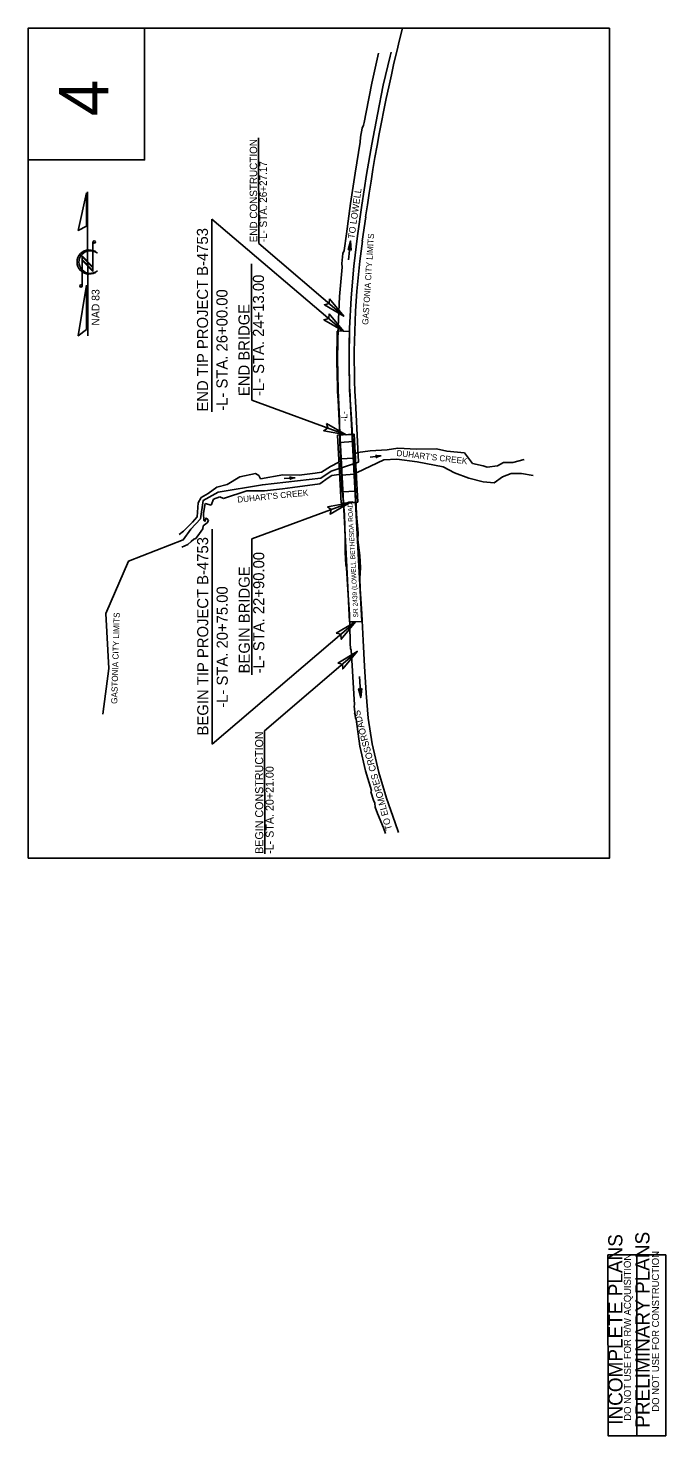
# Model space of a CAD drawing. Extents: x 1372027 to 1374286, y 553832 to 556743.
# Drawn here: x 1373433 to 1373952, y 555599 to 556743 of the extents above; entities that cross this region are included whole.
import ezdxf

# ---------------------------------------------------------------- set-up
doc = ezdxf.new("R2010")
doc.units = 0
for name, color, linetype in [('Default', 7, 'Continuous'), ('Prop Dimension', 7, 'Continuous'), ('Prop Dimension Text', 7, 'Continuous'), ('Prop EOT', 7, 'Continuous'), ('Prop Horizontal Alignment', 7, 'Continuous'), ('Prop Horizontal Alignment Curve and Spiral Data', 7, 'Continuous'), ('Prop Horizontal Alignment Station Label', 7, 'Continuous'), ('Prop Horizontal Alignment Tick Small', 7, 'Continuous'), ('Prop North Arrow for Plan Sheets CELL', 7, 'Continuous'), ('Prop Roadway Bridge', 7, 'Continuous'), ('Prop Shade Light', 7, 'Continuous'), ('Prop Terminator CELL', 7, 'Continuous'), ('Sheet Layout Plan Border', 7, 'Continuous'), ('Sheet North Arrow CELL', 7, 'Continuous'), ('Sheet Plan Layout CELL', 7, 'Continuous'), ('Sheet Plot Border Inside CELL', 7, 'Continuous')]:
    doc.layers.add(name, color=color, linetype=linetype)

msp = doc.modelspace()

# ---------------------------------------------------------------- linework, layer by layer
at = {"layer": 'Default'}
for p, q in [((1373693.8, 556554.9), (1373695.4, 556570.2)), ((1373702.6, 556216.3), (1373703.7, 556199.2))]:
    msp.add_line(p, q, dxfattribs=at)
at = {"layer": 'Prop Dimension'}
for p, q in [((1373620.7, 556568.1), (1373620.6, 556654)), ((1373689.6, 556496.9), (1373582.6, 556588)), ((1373582.7, 556431.4), (1373582.6, 556588)), ((1373689.9, 556509.1), (1373620.7, 556568.1)), ((1373615, 556440.9), (1373614.9, 556551.7)), ((1373615, 556440.9), (1373691.7, 556412.8)), ((1373694.5, 556357.6), (1373615.1, 556328.3)), ((1373582.9, 556161.3), (1373582.8, 556336)), ((1373615.2, 556217.7), (1373615.1, 556328.3)), ((1373582.9, 556161.3), (1373699.5, 556260.9)), ((1373625.5, 556172.3), (1373700.8, 556236.7)), ((1373625.6, 556072.3), (1373625.5, 556172.3))]:
    msp.add_line(p, q, dxfattribs=at)
at = {"layer": 'Prop Dimension Text'}
for p, q in [((1373684.9, 556412.5), (1373698.4, 556413.2)), ((1373687.8, 556357.2), (1373684.9, 556412.5)), ((1373698.4, 556413.2), (1373701.3, 556357.9)), ((1373701.3, 556357.9), (1373687.8, 556357.2))]:
    msp.add_line(p, q, dxfattribs=at)
for points in [[(1373433.3, 556068.7), (1373433.3, 556743.1), (1373905.8, 556743.1), (1373905.8, 556068.7)], [(1373433.3, 556636.1), (1373433.3, 556743.1), (1373528, 556743.1), (1373528, 556636.1)]]:
    msp.add_lwpolyline(points, close=True, dxfattribs=at)
at = {"layer": 'Prop EOT'}
for p, q in [((1373684.6, 556497.1), (1373694.5, 556496.8)), ((1373692.3, 556305.6), (1373685.3, 556440.9)), ((1373704.5, 556261.2), (1373695.2, 556441.4)), ((1373692.3, 556305.6), (1373694.6, 556260.7)), ((1373694.6, 556260.7), (1373699.5, 556260.9)), ((1373699.5, 556260.9), (1373704.5, 556261.2))]:
    msp.add_line(p, q, dxfattribs=at)
for radius in [695.7, 685.8]:
    msp.add_arc((1374380, 556476.8), radius, 178.3325, 182.9585, dxfattribs=at)
at = {"layer": 'Prop Horizontal Alignment'}
msp.add_lwpolyline([(1373951.7, 555599.5), (1373928.2, 555599.5), (1373928.1, 555746.5), (1373951.6, 555746.5)], close=True, dxfattribs=at)
at = {"layer": 'Prop Horizontal Alignment Curve and Spiral Data'}
for p, q in [((1373687.3, 556393.2), (1373698, 556393.9)), ((1373698.6, 556380.7), (1373687.9, 556380))]:
    msp.add_line(p, q, dxfattribs=at)
msp.add_lwpolyline([(1373699.5, 556367), (1373688.5, 556366.3), (1373686.6, 556406.6), (1373697.5, 556407.3), (1373699.5, 556367)], dxfattribs=at)
at = {"layer": 'Prop Horizontal Alignment Tick Small'}
msp.add_lwpolyline([(1373928.2, 555599.5), (1373904.7, 555599.5), (1373904.6, 555746.5), (1373928.1, 555746.5)], close=True, dxfattribs=at)
at = {"layer": 'Prop North Arrow for Plan Sheets CELL'}
for points in [[(1373693.4, 556563.1), (1373695.4, 556570.2), (1373696, 556562.8), (1373694.8, 556563.9)], [(1373704.5, 556206.5), (1373703.7, 556199.2), (1373701.9, 556206.4), (1373703.3, 556205.6)]]:
    msp.add_lwpolyline(points, close=True, dxfattribs=at)
at = {"layer": 'Prop Roadway Bridge'}
for p, q in [((1373684.9, 556412.5), (1373698.4, 556413.2)), ((1373687.8, 556357.2), (1373684.9, 556412.5)), ((1373701.3, 556357.9), (1373698.4, 556413.2)), ((1373687.8, 556357.2), (1373701.3, 556357.9))]:
    msp.add_line(p, q, dxfattribs=at)
at = {"layer": 'Prop Shade Light'}
msp.add_line((1373685.3, 556440.9), (1373686.7, 556412.6), dxfattribs=at)
for points in [[(1373694.5, 556496.8), (1373689.6, 556496.9), (1373684.6, 556497.1)], [(1373686.7, 556412.6), (1373696.6, 556413.1), (1373695.2, 556441.4)]]:
    msp.add_lwpolyline(points, dxfattribs=at)
msp.add_lwpolyline([(1373699.5, 556357.8), (1373689.6, 556357.3), (1373692.3, 556305.6), (1373694.6, 556260.7), (1373699.5, 556260.9), (1373704.5, 556261.2), (1373702.1, 556306.1)], close=True, dxfattribs=at)
for radius in [695.7, 685.8]:
    msp.add_arc((1374380, 556476.8), radius, 178.3325, 182.9585, dxfattribs=at)
at = {"layer": 'Prop Terminator CELL'}
for points in [[(1373704.9, 556570), (1373707.7, 556589.8)], [(1373701.9, 556390.6), (1373699.3, 556440)], [(1373493.9, 556185.7), (1373498.9, 556222.8), (1373496.4, 556267.5), (1373514.9, 556310.1), (1373559.4, 556327.4), (1373565.5, 556336), (1373573.4, 556344.6), (1373575.6, 556359.4), (1373587.9, 556366.2), (1373623.8, 556372.2), (1373671.1, 556377.6), (1373679.6, 556383.3), (1373693, 556387.5), (1373701.9, 556390.6)]]:
    msp.add_lwpolyline(points, dxfattribs=at)
for points in [[(1373678.2, 556523.2), (1373689.9, 556509.1), (1373674.1, 556518.4), (1373677.9, 556519.4)], [(1373677.9, 556511), (1373689.6, 556496.9), (1373673.7, 556506.2), (1373677.6, 556507.2)], [(1373675.8, 556421.9), (1373691.7, 556412.8), (1373673.6, 556416), (1373676.8, 556418.3)], [(1373676.6, 556354.3), (1373694.5, 556357.6), (1373678.7, 556348.3), (1373679.7, 556352.1)], [(1373683.8, 556251.6), (1373699.5, 556260.9), (1373687.8, 556246.7), (1373687.5, 556250.7)], [(1373685.1, 556227.3), (1373700.8, 556236.7), (1373689.1, 556222.5), (1373688.8, 556226.4)]]:
    msp.add_lwpolyline(points, close=True, dxfattribs=at)
for centre, radius, start, end in [((1375157.8, 556386.7), 1464.3, 165.9137, 172.027), ((1374376.9, 556475.9), 678.5, 172.027, 183.0355)]:
    msp.add_arc(centre, radius, start, end, dxfattribs=at)
at = {"layer": 'Sheet Layout Plan Border'}
for p, q in [((1373698.9, 556397.3), (1373701.2, 556398.5)), ((1373699.4, 556394.6), (1373698.9, 556397.3)), ((1373701.2, 556398.5), (1373711.4, 556399.8)), ((1373720.2, 556395.7), (1373711.3, 556394.5)), ((1373711.4, 556399.8), (1373725.1, 556400.5)), ((1373715.6, 556396.1), (1373716.5, 556395.9)), ((1373715.8, 556395.1), (1373715.8, 556395.1)), ((1373716.5, 556395.9), (1373717.4, 556395.7)), ((1373717.4, 556395.7), (1373718.4, 556395.6)), ((1373717.5, 556394.9), (1373718.4, 556395.3)), ((1373718.4, 556395.6), (1373719.3, 556395.6)), ((1373718.4, 556395.3), (1373719.3, 556395.5)), ((1373719.3, 556395.5), (1373720.2, 556395.7)), ((1373719.3, 556395.6), (1373720.2, 556395.7)), ((1373725.1, 556400.5), (1373733.9, 556401.9)), ((1373733.9, 556401.9), (1373749.1, 556401.2)), ((1373749.1, 556401.2), (1373765.2, 556401.3)), ((1373765.2, 556401.3), (1373773.7, 556399.4)), ((1373773.7, 556399.4), (1373788.1, 556398.2)), ((1373788.1, 556398.2), (1373794.6, 556389.4)), ((1373671.8, 556382.4), (1373679, 556387.1)), ((1373679, 556387.1), (1373685.9, 556390.4)), ((1373685.9, 556390.4), (1373687.3, 556391.9)), ((1373698.2, 556393.2), (1373699.4, 556393.2)), ((1373699.4, 556393.2), (1373699.4, 556394.6)), ((1373700.7, 556382), (1373722.4, 556392.3)), ((1373715.9, 556394.1), (1373716.7, 556394.5)), ((1373716.7, 556394.5), (1373717.5, 556394.9)), ((1373722.4, 556392.3), (1373733, 556393)), ((1373733, 556393), (1373749.6, 556390.7)), ((1373749.6, 556390.7), (1373770.6, 556386.8)), ((1373770.6, 556386.8), (1373779.8, 556381.9)), ((1373794.6, 556389.4), (1373803.1, 556387.6)), ((1373803.1, 556387.6), (1373806.4, 556386.4)), ((1373806.4, 556386.4), (1373814.9, 556387.5)), ((1373814.9, 556387.5), (1373819.6, 556390.2)), ((1373819.6, 556390.2), (1373827.4, 556390.3)), ((1373827.4, 556390.3), (1373836.4, 556392.8)), ((1373586.6, 556370.1), (1373595.1, 556372.5)), ((1373595.1, 556372.5), (1373605.4, 556378.7)), ((1373605.4, 556378.7), (1373618.2, 556381.2)), ((1373618.2, 556381.2), (1373620.7, 556379.6)), ((1373620.7, 556379.6), (1373622.3, 556377.1)), ((1373622.3, 556377.1), (1373640.3, 556380.2)), ((1373640.3, 556380.2), (1373653.5, 556380)), ((1373650.3, 556377.9), (1373641.4, 556377.2)), ((1373645.8, 556378.6), (1373646.7, 556378.3)), ((1373645.9, 556377.6), (1373645.9, 556377.6)), ((1373645.9, 556376.5), (1373646.8, 556377)), ((1373646.7, 556378.3), (1373647.6, 556378.1)), ((1373646.8, 556377), (1373647.6, 556377.3)), ((1373647.6, 556378.1), (1373648.5, 556377.9)), ((1373647.6, 556377.3), (1373648.5, 556377.6)), ((1373648.3, 556370), (1373670.4, 556372.8)), ((1373648.5, 556377.9), (1373649.4, 556377.9)), ((1373648.5, 556377.6), (1373649.4, 556377.8)), ((1373649.4, 556377.8), (1373650.3, 556377.9)), ((1373649.4, 556377.9), (1373650.3, 556377.9)), ((1373653.5, 556380), (1373666.6, 556381.5)), ((1373666.6, 556381.5), (1373671.8, 556382.4)), ((1373670.4, 556372.8), (1373677.2, 556377.9)), ((1373677.2, 556377.9), (1373680.2, 556379.6)), ((1373680.2, 556379.6), (1373685.9, 556380.4)), ((1373698.8, 556381.6), (1373700.7, 556382)), ((1373779.8, 556381.9), (1373791.6, 556377.4)), ((1373791.6, 556377.4), (1373803.2, 556374.5)), ((1373803.2, 556374.5), (1373812.2, 556373.7)), ((1373812.2, 556373.7), (1373819, 556378.7)), ((1373819, 556378.7), (1373825.9, 556381.3)), ((1373825.9, 556381.3), (1373834.4, 556381.3)), ((1373834.4, 556381.3), (1373843.9, 556379.7)), ((1373571.6, 556357.6), (1373574, 556361.8)), ((1373574, 556361.8), (1373579.6, 556365.1)), ((1373579.6, 556365.1), (1373586.6, 556370.1)), ((1373584.1, 556360.5), (1373589.2, 556362.3)), ((1373589.2, 556362.3), (1373592.1, 556361)), ((1373592.1, 556361), (1373611.1, 556367.2)), ((1373611.1, 556367.2), (1373625.4, 556367.3)), ((1373625.4, 556367.3), (1373640, 556368.9)), ((1373640, 556368.9), (1373648.3, 556370)), ((1373570.8, 556346.2), (1373571.6, 556357.6)), ((1373570.8, 556346.2), (1373571.6, 556357.6)), ((1373575.8, 556349.2), (1373577.2, 556357)), ((1373577.2, 556357), (1373582.2, 556355.5)), ((1373582.2, 556355.5), (1373584.1, 556360.5)), ((1373559.7, 556334.4), (1373566.8, 556341.9)), ((1373566.8, 556341.9), (1373570.8, 556346.2)), ((1373575.2, 556336.3), (1373575.7, 556338.9)), ((1373575.7, 556338.9), (1373578.7, 556341.1)), ((1373576.1, 556343.1), (1373575.8, 556349.2)), ((1373576.8, 556342.4), (1373576.1, 556343.1)), ((1373578.1, 556345.2), (1373576.8, 556342.4)), ((1373578.6, 556344.8), (1373578.1, 556345.2)), ((1373579.9, 556343.2), (1373578.6, 556344.8)), ((1373578.7, 556341.1), (1373579.9, 556343.2)), ((1373556.1, 556331.8), (1373559.7, 556334.4)), ((1373565.7, 556326), (1373567.9, 556327.9)), ((1373567.9, 556327.9), (1373569.5, 556328.6)), ((1373569.5, 556328.6), (1373572.6, 556332.6)), ((1373572.6, 556332.6), (1373575.2, 556336.3)), ((1373558.2, 556321.4), (1373563, 556323.6)), ((1373563, 556323.6), (1373565.7, 556326))]:
    msp.add_line(p, q, dxfattribs=at)
at = {"layer": 'Sheet North Arrow CELL'}
for p, q in [((1373481.7, 556493.2), (1373481.6, 556610.2)), ((1373486, 556569.5), (1373486, 556545.5)), ((1373486, 556549.2), (1373477.1, 556558.1)), ((1373477.1, 556558.1), (1373477.1, 556533.7)), ((1373486, 556548.3), (1373477.1, 556557.3)), ((1373477.1, 556557.3), (1373477.1, 556555.1)), ((1373489.3, 556560.5), (1373489.5, 556560.4)), ((1373486, 556546.1), (1373477.1, 556555.1)), ((1373477.1, 556555.1), (1373486, 556546.1)), ((1373486, 556545.5), (1373477.1, 556554.4)), ((1373486, 556546.1), (1373486, 556548.3))]:
    msp.add_line(p, q, dxfattribs=at)
for points in [[(1373480.8, 556609.2), (1373474.1, 556578.8), (1373480.8, 556582.2)], [(1373480.7, 556534.4), (1373474.1, 556493.2), (1373480.7, 556498.4)]]:
    msp.add_lwpolyline(points, close=True, dxfattribs=at)
for centre in [(1373487, 556569.4), (1373476.2, 556533.7)]:
    msp.add_circle(centre, 0.954, dxfattribs=at)
for centre, radius, start, end in [((1373482.9, 556553.1), 9.83, 47.891, 312.445), ((1373483.8, 556553.1), 9.21, 53.146, 308.6797)]:
    msp.add_arc(centre, radius, start, end, dxfattribs=at)
at = {"layer": 'Sheet Plot Border Inside CELL'}
for points in [[(1373686.7, 556406.7), (1373686.3, 556425.7), (1373685.3, 556448.7), (1373684.8, 556474.9), (1373685.3, 556500.3), (1373686.3, 556525), (1373688.6, 556549), (1373688.2, 556551.8), (1373689.2, 556560.1), (1373690.1, 556562.4), (1373692, 556576), (1373695.4, 556600.7), (1373699.2, 556625.3), (1373703.3, 556650.5), (1373703.4, 556654.5), (1373704.9, 556661.9), (1373705.8, 556664.3), (1373706.5, 556666.6), (1373708.1, 556674.8), (1373712.8, 556698.5), (1373718.1, 556722.7)], [(1373728.4, 556723.6), (1373727.5, 556720.4), (1373722, 556696.7), (1373717.3, 556673.1), (1373712.7, 556648.8), (1373708.4, 556624.1), (1373704.6, 556599.3), (1373701.1, 556574.4), (1373698, 556549.8), (1373695.9, 556524.1), (1373694.6, 556499), (1373694.3, 556474.4), (1373694.6, 556449.3), (1373696.1, 556425.4), (1373697.2, 556407.7)], [(1373702.8, 556159.9), (1373699.9, 556181.7), (1373699.3, 556182.4), (1373698.2, 556192.2), (1373698.6, 556193.4), (1373698.1, 556202.4), (1373696.6, 556225.4), (1373695.9, 556237.7), (1373695.4, 556239), (1373695.2, 556243.1), (1373695.2, 556245.6), (1373694.4, 556266.7), (1373693.2, 556286.9), (1373692, 556304.6), (1373691.6, 556307.1), (1373691.1, 556317.5), (1373690.9, 556327.6), (1373690.4, 556347.9), (1373688.9, 556366.1)], [(1373699.3, 556366.7), (1373700.2, 556348.4), (1373701.5, 556332.7), (1373701.3, 556327.7), (1373703, 556314.6), (1373703.4, 556304.7), (1373703, 556296.4), (1373703.2, 556287.7), (1373704.5, 556267.2), (1373705.7, 556245.6), (1373706.8, 556224.8), (1373708, 556202.9), (1373709.8, 556182.5), (1373713, 556161.6), (1373718.5, 556138.5), (1373724.7, 556117.6), (1373731.6, 556097.4), (1373734.4, 556089.6)], [(1373723.8, 556088.7), (1373722.1, 556093.5), (1373717.2, 556105.2), (1373715.4, 556110.2), (1373715.1, 556113.4), (1373713.9, 556115.9), (1373712, 556122.6), (1373712.3, 556123.7), (1373707.5, 556139.7), (1373702.8, 556159.9)]]:
    msp.add_lwpolyline(points, dxfattribs=at)

# ---------------------------------------------------------------- texts
at = {"layer": 'Default'}
for s, height, rotation, p in [('TO LOWELL', 5.4, 81.8863, (1373698.5, 556571.7)), ('GASTONIA CITY LIMITS', 4.95, 86.228, (1373709.7, 556502)), ("DUHART'S CREEK", 4.95, 353.2921, (1373732.5, 556395.6)), ("DUHART'S CREEK", 4.95, 5.7449, (1373603.6, 556357.6)), ('SR 2439 (LOWELL BETHESDA ROAD)', 3.888, 92.999, (1373701.7, 556264.4)), ('GASTONIA CITY LIMITS', 4.95, 88.3665, (1373505.7, 556194.1)), ('TO ELMORES CROSSROADS', 5.4, 105.2493, (1373729.3, 556092.3))]:
    msp.add_text(s, height=height, rotation=rotation, dxfattribs=at).set_placement(p)
at = {"layer": 'Prop Dimension Text'}
msp.add_text('4', height=40, rotation=90.0509, dxfattribs=at).set_placement((1373498.5, 556671.6))
at = {"layer": 'Prop Horizontal Alignment'}
for s, height, p in [('PRELIMINARY PLANS', 11.52, (1373938.5, 555606)), ('DO NOT USE FOR CONSTRUCTION', 5.76, (1373946.2, 555619.1))]:
    msp.add_text(s, height=height, rotation=90.0509, dxfattribs=at).set_placement(p)
at = {"layer": 'Prop Horizontal Alignment Station Label'}
msp.add_text('-L-', height=5.12, rotation=92.9763, dxfattribs=at).set_placement((1373693, 556423.7))
at = {"layer": 'Prop Horizontal Alignment Tick Small'}
for s, height, p in [('INCOMPLETE PLANS', 11.52, (1373916.5, 555608.4)), ('DO NOT USE FOR R/W ACQUISITION', 5.76, (1373923.4, 555611.7))]:
    msp.add_text(s, height=height, rotation=90.0509, dxfattribs=at).set_placement(p)
at = {"layer": 'Sheet North Arrow CELL'}
msp.add_text('NAD 83', height=6.3, rotation=90.0509, dxfattribs=at).set_placement((1373491.3, 556501.5))
at = {"layer": 'Sheet Plan Layout CELL'}
for s, height, p in [('END CONSTRUCTION', 6, (1373619.5, 556569.2)), ('-L- STA. 26+27.17', 6, (1373627.4, 556569.2)), ('END TIP PROJECT B-4753', 9, (1373579.6, 556431.6)), ('-L- STA. 24+13.00', 9, (1373625.1, 556444.2)), ('-L- STA. 26+00.00 ', 9, (1373595.4, 556432.3)), ('END BRIDGE', 9, (1373613.3, 556444.2)), ('BEGIN TIP PROJECT B-4753', 9, (1373579.8, 556168.5)), ('-L- STA. 22+90.00', 9, (1373625.3, 556218.9)), ('BEGIN BRIDGE', 9, (1373613.5, 556218.9)), ('-L- STA. 20+75.00 ', 9, (1373595.6, 556191)), ('BEGIN CONSTRUCTION', 6.5, (1373624.4, 556072.3)), ('-L- STA. 20+21.00', 6.5, (1373632.9, 556072.3))]:
    msp.add_text(s, height=height, rotation=90.0509, dxfattribs=at).set_placement(p)

doc.saveas('drawing.dxf')
